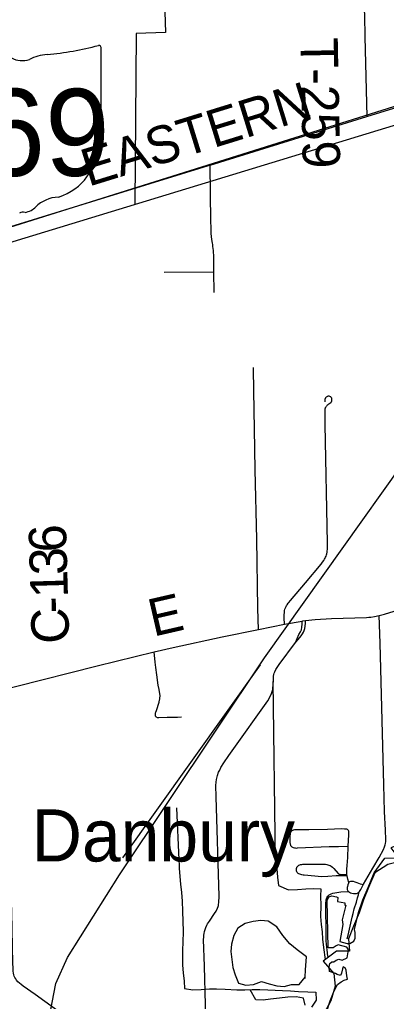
# Model space of a CAD drawing. Extents: x 0 to 34, y 0 to 22.
# Drawn here: x 6.521 to 6.799, y 17.764 to 18.509 of the extents above; entities that cross this region are included whole.
import ezdxf

# ---------------------------------------------------------------- set-up
doc = ezdxf.new("R2010")
doc.units = 0
for name, color, linetype in [('GM_X_Corporation', 7, 'Continuous'), ('GM_X_County_Road', 7, 'Continuous'), ('GM_X_County_Road_Text', 7, 'Continuous'), ('GM_X_Major_Lake', 7, 'Continuous'), ('GM_X_Minor_River', 7, 'Continuous'), ('GM_X_Rail_Line', 7, 'Continuous'), ('GM_X_State_Shield', 7, 'Continuous'), ('GM_X_Township_Road', 7, 'Continuous'), ('GM_X_Township_Road_Text', 7, 'Continuous'), ('GM_X_Unincorporated_Text', 7, 'Continuous')]:
    doc.layers.add(name, color=color, linetype=linetype)

msp = doc.modelspace()

# ---------------------------------------------------------------- linework, layer by layer
at = {"layer": 'GM_X_Corporation'}
msp.add_lwpolyline([(6.75001, 17.74515), (6.75626, 17.76472), (6.75934, 17.77212), (6.76173, 17.77704), (6.76463, 17.77893), (6.7669, 17.78019), (6.76942, 17.78094), (6.76879, 17.78359), (6.76841, 17.78788), (6.76766, 17.78952), (6.76602, 17.79027), (6.76551, 17.78876), (6.76488, 17.78548), (6.76413, 17.78372), (6.76161, 17.7846), (6.76034, 17.78536), (6.75581, 17.78674), (6.75556, 17.79015), (6.75606, 17.79292), (6.75745, 17.79406), (6.75909, 17.79406), (6.76085, 17.79544), (6.76287, 17.79607), (6.76526, 17.79532), (6.76917, 17.79708), (6.77021, 17.80321), (6.76879, 17.80527), (6.76236, 17.80704), (6.76072, 17.80628), (6.75858, 17.80477), (6.7548, 17.80477), (6.75404, 17.8407), (6.75518, 17.84347), (6.75757, 17.84422), (6.76097, 17.84334), (6.76211, 17.84297), (6.76186, 17.83994), (6.76728, 17.83881), (6.76728, 17.83717), (6.76803, 17.83704), (6.76526, 17.82595), (6.76589, 17.82254), (6.76362, 17.80969), (6.76904, 17.80817), (6.77106, 17.80817), (6.77409, 17.80981), (6.77522, 17.81221), (6.77522, 17.81649), (6.77459, 17.81876), (6.7777, 17.83145), (6.78111, 17.84114), (6.78491, 17.85065), (6.78965, 17.86168), (6.79761, 17.87284), (6.80592, 17.87307)], dxfattribs=at)
at = {"layer": 'GM_X_County_Road'}
for p, q in [((6.72168, 18.05033), (6.73492, 18.0526)), ((6.70197, 18.04626), (6.72168, 18.05033))]:
    msp.add_line(p, q, dxfattribs=at)
for points in [[(6.78405, 18.4351), (6.84223, 18.45323), (6.86594, 18.46076), (6.94588, 18.48653), (7.00216, 18.50455), (7.05407, 18.521), (7.05859, 18.52222), (7.0626, 18.52332)], [(6.6654, 18.39833), (6.76948, 18.43055), (6.78405, 18.4351)], [(6.4999, 18.34733), (6.50494, 18.34889), (6.53465, 18.35812), (6.66398, 18.39789), (6.6654, 18.39833)], [(6.79337, 18.0568), (6.79733, 18.05769), (6.8047, 18.06002), (6.81208, 18.06286)], [(6.73492, 18.0526), (6.73549, 18.0527), (6.73752, 18.05295), (6.74478, 18.05383), (6.75723, 18.05451), (6.78366, 18.05528), (6.78549, 18.05542), (6.78713, 18.05564), (6.78978, 18.056), (6.79337, 18.0568)], [(6.62285, 18.02934), (6.63733, 18.03241), (6.67444, 18.04055), (6.70197, 18.04626)], [(6.50954, 18.00084), (6.51779, 18.00287), (6.57959, 18.01851), (6.62285, 18.02934)]]:
    msp.add_lwpolyline(points, dxfattribs=at)
at = {"layer": 'GM_X_Major_Lake'}
for points in [[(6.80771, 17.89166), (6.81611, 17.88635), (6.82067, 17.87666), (6.82523, 17.86697), (6.81574, 17.87457), (6.81175, 17.88407), (6.80226, 17.88065), (6.80985, 17.87058), (6.79998, 17.86791), (6.79012, 17.86164), (6.78537, 17.85061), (6.78158, 17.84111), (6.77816, 17.83141), (6.7738, 17.82114)], [(6.80775, 17.89141), (6.81611, 17.88635), (6.82067, 17.87666), (6.82523, 17.86697), (6.81574, 17.87457), (6.81175, 17.88407), (6.80226, 17.88065), (6.80985, 17.87058), (6.79998, 17.86791), (6.79012, 17.86164), (6.78537, 17.85061), (6.78158, 17.84111), (6.77816, 17.83141), (6.7738, 17.82114)], [(6.7738, 17.82114), (6.77, 17.81164), (6.77076, 17.80213), (6.76108, 17.80232), (6.75084, 17.79472), (6.759, 17.78521), (6.75995, 17.77571), (6.75672, 17.76468), (6.7516, 17.75518)]]:
    msp.add_lwpolyline(points, dxfattribs=at)
at = {"layer": 'GM_X_Minor_River'}
for points in [[(6.62619, 18.663), (6.63139, 18.49883), (6.60918, 18.49815), (6.60813, 18.36834)], [(6.97961, 18.48166), (6.49479, 18.33379), (6.49906, 18.20382), (6.46737, 18.20215), (6.46468, 18.20803), (6.44, 18.20753), (6.41565, 18.21882)], [(6.70311, 18.01948), (6.59888, 17.87304)], [(6.71266, 18.0068), (6.71449, 17.8713)], [(6.63988, 17.91086), (6.6416, 17.87153)], [(6.6415, 17.87368), (6.64177, 17.86525), (6.6422, 17.85896), (6.64283, 17.85305), (6.64364, 17.84676), (6.64407, 17.84028), (6.64428, 17.83248), (6.64467, 17.82468), (6.6447, 17.81745), (6.64451, 17.80889), (6.6442, 17.80339), (6.64427, 17.79768), (6.64432, 17.79159), (6.64476, 17.78588), (6.64557, 17.77939), (6.64583, 17.77387), (6.65209, 17.77297), (6.65837, 17.77321), (6.66466, 17.77364), (6.67018, 17.77371), (6.67664, 17.77338), (6.68538, 17.77299), (6.69146, 17.77286), (6.69718, 17.77311), (6.70289, 17.77317), (6.70897, 17.77304), (6.71467, 17.77272), (6.72018, 17.77241), (6.72607, 17.77209), (6.73234, 17.77176), (6.73937, 17.77141), (6.74546, 17.77128), (6.74551, 17.76519), (6.74197, 17.75975)], [(6.71448, 17.87235), (6.71576, 17.86474), (6.71619, 17.85827), (6.717, 17.85197), (6.72473, 17.84876), (6.73139, 17.84899), (6.73768, 17.84942), (6.74359, 17.84986), (6.7491, 17.84955), (6.74897, 17.84385), (6.7492, 17.837), (6.74882, 17.82845), (6.74945, 17.82254), (6.75009, 17.81701), (6.75053, 17.81129), (6.75115, 17.805), (6.75246, 17.79593)], [(6.73822, 17.79804), (6.73133, 17.80316), (6.72572, 17.80785), (6.72035, 17.81424), (6.71593, 17.82081), (6.70936, 17.82495), (6.70367, 17.82546), (6.69775, 17.82483), (6.69182, 17.82325), (6.68623, 17.81976), (6.68325, 17.81412), (6.68139, 17.8075), (6.68089, 17.802), (6.6817, 17.79589)], [(6.73822, 17.79804), (6.73133, 17.80316), (6.72572, 17.80785), (6.72035, 17.81424), (6.71593, 17.82081), (6.70936, 17.82495), (6.70367, 17.82546), (6.69775, 17.82483), (6.69182, 17.82325), (6.68623, 17.81976), (6.68325, 17.81412), (6.68139, 17.8075), (6.68089, 17.802), (6.6817, 17.79589), (6.68252, 17.78998), (6.68411, 17.78424), (6.68663, 17.77791), (6.6923, 17.77645), (6.69802, 17.77689), (6.70416, 17.77923), (6.71002, 17.77758), (6.71569, 17.77593), (6.72139, 17.77542), (6.72694, 17.77701), (6.73265, 17.77708), (6.73733, 17.78249), (6.73765, 17.788), (6.73822, 17.79804)], [(6.6817, 17.79589), (6.68252, 17.78998), (6.68411, 17.78424), (6.68663, 17.77791), (6.6923, 17.77645), (6.69802, 17.77689), (6.70416, 17.77923), (6.71002, 17.77758), (6.71569, 17.77593), (6.72139, 17.77542), (6.72694, 17.77701), (6.73265, 17.77708), (6.73733, 17.78249), (6.73765, 17.788), (6.73822, 17.79804)], [(6.73731, 17.78154), (6.7373, 17.78292)], [(6.73724, 17.76119), (6.73603, 17.76673), (6.73035, 17.76762), (6.72425, 17.76737), (6.71777, 17.76657), (6.71109, 17.76576), (6.70537, 17.76513), (6.69986, 17.76525), (6.69564, 17.77304)]]:
    msp.add_lwpolyline(points, dxfattribs=at)
at = {"layer": 'GM_X_Rail_Line'}
for points in [[(4.40206, 18.19809), (4.68917, 18.19409), (5.00635, 18.18976), (5.15875, 18.1876), (5.36248, 18.18265), (5.7183, 18.17956), (5.93191, 18.17708), (6.25187, 18.2714), (6.49949, 18.34686), (7.04327, 18.51787), (7.07913, 18.52777), (7.1289, 18.52993), (7.24173, 18.53643), (7.28965, 18.56333), (7.33819, 18.59766)], [(6.61278, 17.58757), (6.59394, 17.63538), (6.57825, 17.66366), (6.55382, 17.71187), (6.54839, 17.72205), (6.54535, 17.73648), (6.54431, 17.75668), (6.54839, 17.77773), (6.55721, 17.79742), (6.59664, 17.86024), (6.70636, 18.02469), (6.87002, 18.25426), (6.98718, 18.4243), (7.02028, 18.46299), (7.04296, 18.48014), (7.06305, 18.4922), (7.09953, 18.50612), (7.1255, 18.5154), (7.18609, 18.52653), (7.59084, 18.53815)]]:
    msp.add_lwpolyline(points, dxfattribs=at)
at = {"layer": 'GM_X_State_Shield'}
for p, q in [((6.58263, 18.43502), (6.58263, 18.48737)), ((6.58262, 18.43504), (6.58263, 18.43502))]:
    msp.add_line(p, q, dxfattribs=at)
for centre, major_axis, start_param, end_param in [((6.52393, 18.6213), (0.17476, 0), 4.814394, 5.042369), ((6.5808, 18.48758), (0.00183, 0), 6.141152, 7.989035), ((6.52262, 18.48819), (0.01336, 0), 4.081561, 5.145723), ((6.54622, 18.45432), (0.03516, 0), 1.699011, 2.107814), ((6.58221, 18.43118), (0.00284, 0), 1.883978, 3.671073), ((6.58067, 18.43482), (0.00196, 0), 5.05454, 6.418171), ((6.56415, 18.42456), (0.01704, 0), 5.934695, 6.695948), ((6.5892, 18.41312), (0.0124, 0), 2.387724, 3.262537), ((6.53372, 18.40646), (0.04371, 0), 5.101752, 6.440018), ((6.55215, 18.35501), (0.02394, 0), 1.647645, 2.488434), ((6.52182, 18.37341), (0.01412, 0), 4.937069, 5.64225), ((6.52342, 18.35965), (0.00376, 0), 1.147584, 2.315152)]:
    msp.add_ellipse(centre, major_axis=major_axis, ratio=0.8, start_param=start_param, end_param=end_param, dxfattribs=at)
at = {"layer": 'GM_X_Township_Road'}
for p, q in [((6.63034, 18.3171), (6.66809, 18.31732)), ((6.66831, 18.30179), (6.66809, 18.31732)), ((6.76912, 17.85943), (6.76898, 17.86034))]:
    msp.add_line(p, q, dxfattribs=at)
for points in [[(6.78102, 18.51649), (6.78136, 18.51609), (6.78172, 18.5155), (6.78185, 18.51522), (6.78194, 18.51491), (6.78206, 18.51436), (6.78213, 18.51385), (6.78218, 18.51332), (6.78218, 18.51276), (6.78221, 18.5117), (6.7824, 18.4956), (6.78405, 18.4351)], [(6.66809, 18.31732), (6.66803, 18.32288), (6.66797, 18.32853), (6.66769, 18.33356), (6.66758, 18.33507), (6.66741, 18.33647), (6.66719, 18.338), (6.667, 18.33905), (6.66651, 18.34184), (6.66629, 18.34414), (6.66612, 18.34649), (6.66595, 18.34911), (6.66592, 18.35097), (6.66584, 18.35566), (6.6654, 18.39833)], [(6.70197, 18.04626), (6.70147, 18.06206), (6.70054, 18.11471), (6.69945, 18.16736), (6.69892, 18.19833), (6.69867, 18.21226), (6.69811, 18.24322), (6.6981, 18.24477)], [(6.72168, 18.05033), (6.72146, 18.0549), (6.72145, 18.05757), (6.7215, 18.05892), (6.72158, 18.05992), (6.72171, 18.06063), (6.72193, 18.06147), (6.72216, 18.06214), (6.72252, 18.06299), (6.72278, 18.06354), (6.72326, 18.06432), (6.7237, 18.06492), (6.72446, 18.06603), (6.72494, 18.06668), (6.72617, 18.0682), (6.73743, 18.08161), (6.74938, 18.09575), (6.75047, 18.09712), (6.75132, 18.09838), (6.75197, 18.09951), (6.75245, 18.10036), (6.75277, 18.10104), (6.75314, 18.10185), (6.7535, 18.10287), (6.75371, 18.10367), (6.75391, 18.10477), (6.75403, 18.10561), (6.75416, 18.10708), (6.75427, 18.10893), (6.75432, 18.11173), (6.75241, 18.20166), (6.75242, 18.21158), (6.75242, 18.2127), (6.75245, 18.21325), (6.75251, 18.21373), (6.75257, 18.21412), (6.75272, 18.21449), (6.75308, 18.21504), (6.75346, 18.21552), (6.75368, 18.21579), (6.754, 18.21611), (6.75432, 18.21643), (6.75481, 18.21683), (6.75533, 18.21726), (6.75666, 18.21835), (6.75698, 18.21866), (6.75719, 18.21891), (6.75746, 18.21949), (6.75753, 18.2198), (6.75758, 18.22018), (6.75758, 18.22076), (6.75752, 18.22121), (6.75741, 18.22152), (6.75726, 18.22181), (6.75706, 18.22212), (6.75671, 18.22248), (6.75643, 18.22271), (6.75595, 18.22297), (6.75558, 18.22308), (6.75526, 18.22309), (6.7545, 18.22303), (6.75415, 18.22293), (6.75366, 18.22271), (6.75321, 18.22237), (6.75281, 18.22193), (6.75259, 18.22156), (6.75245, 18.22126), (6.75225, 18.22049), (6.75219, 18.22018), (6.75216, 18.21974), (6.75214, 18.21927), (6.75215, 18.2188)], [(6.72987, 18.03633), (6.7321, 18.03862), (6.73421, 18.04133), (6.73525, 18.04282), (6.73597, 18.04425), (6.73652, 18.04535), (6.73701, 18.04688), (6.73726, 18.04868), (6.73746, 18.05088), (6.73752, 18.05295)], [(6.72987, 18.03633), (6.73259, 18.04237), (6.73369, 18.04445), (6.73441, 18.04599), (6.73473, 18.04796), (6.73492, 18.0503), (6.73492, 18.0526)], [(6.78119, 17.85249), (6.78153, 17.85313), (6.78856, 17.86523), (6.79335, 17.87336), (6.79655, 17.87924), (6.79743, 17.88127), (6.79792, 17.8828), (6.79818, 17.88399), (6.79835, 17.88531), (6.7984, 17.88698), (6.79809, 17.8941), (6.79747, 17.90811), (6.7968, 17.92834), (6.79408, 18.03589), (6.79337, 18.0568)], [(6.66247, 17.73212), (6.66096, 17.79089), (6.66033, 17.81112), (6.66036, 17.81292), (6.66049, 17.81433), (6.6607, 17.81576), (6.66098, 17.81723), (6.66144, 17.81876), (6.66203, 17.82031), (6.66283, 17.82198), (6.66336, 17.82297), (6.6648, 17.82512), (6.66868, 17.83073), (6.66973, 17.83251), (6.67081, 17.83474), (6.67131, 17.8361), (6.67151, 17.83693), (6.67161, 17.83772), (6.67177, 17.83925), (6.67201, 17.84391), (6.66981, 17.91936), (6.66965, 17.92789), (6.66977, 17.93036), (6.67006, 17.93254), (6.67074, 17.93555), (6.6717, 17.93798), (6.67259, 17.93963), (6.67342, 17.94146), (6.67568, 17.94511), (6.6795, 17.95062), (6.6819, 17.9541), (6.70887, 17.99219), (6.71051, 17.99484), (6.71181, 17.99765), (6.71233, 17.99919), (6.71265, 18.00062), (6.71289, 18.00231), (6.71302, 18.00369), (6.71324, 18.00837), (6.71328, 18.0095), (6.71337, 18.01084), (6.71354, 18.01197), (6.71382, 18.01295), (6.71419, 18.014), (6.715, 18.01579), (6.71748, 18.01975), (6.72987, 18.03633)], [(6.64356, 17.97971), (6.64045, 17.97956), (6.63264, 17.9794), (6.62635, 17.97916), (6.62565, 17.97922), (6.62525, 17.97927), (6.62492, 17.97939), (6.62463, 17.97956), (6.62427, 17.97993), (6.62395, 17.98035), (6.6238, 17.98087), (6.62374, 17.98129), (6.62375, 17.98164), (6.62385, 17.98255), (6.62397, 17.98308), (6.62412, 17.98354), (6.62448, 17.98465), (6.62651, 17.991), (6.62694, 17.9928), (6.62706, 17.99336), (6.62713, 17.99405), (6.62726, 17.99598), (6.62714, 17.99755), (6.62694, 17.99887), (6.62662, 18.00056), (6.62598, 18.00406), (6.62474, 18.01184), (6.62404, 18.01742), (6.62356, 18.02133), (6.62285, 18.02934)], [(6.76999, 17.88189), (6.77045, 17.89046), (6.77045, 17.89152), (6.77045, 17.89229), (6.77042, 17.89271), (6.7703, 17.89332), (6.77009, 17.89378), (6.76981, 17.89411), (6.76938, 17.89445), (6.76887, 17.89466), (6.76839, 17.89477), (6.76777, 17.89485), (6.76701, 17.89487), (6.76484, 17.89491), (6.75412, 17.89449), (6.74012, 17.89434), (6.73208, 17.89425), (6.73036, 17.89424), (6.72962, 17.89423), (6.7292, 17.89422), (6.72832, 17.89408), (6.72795, 17.89393), (6.72758, 17.89375), (6.72718, 17.89351), (6.7268, 17.89321), (6.7265, 17.89283), (6.72623, 17.89234), (6.72604, 17.89188), (6.72594, 17.89157), (6.72579, 17.8908), (6.72574, 17.88988), (6.72571, 17.88898), (6.72568, 17.88771), (6.72573, 17.88474), (6.7259, 17.88351), (6.72607, 17.88297), (6.72629, 17.88248), (6.72654, 17.88215), (6.72688, 17.88172), (6.72729, 17.88142), (6.72767, 17.88118), (6.72822, 17.88087), (6.7291, 17.88063), (6.72993, 17.88052), (6.73088, 17.88047), (6.73158, 17.88049), (6.75559, 17.88151), (6.76249, 17.8817), (6.76999, 17.88189)], [(6.76898, 17.86034), (6.76886, 17.86144), (6.7688, 17.86273), (6.7688, 17.86442), (6.769, 17.86718), (6.76964, 17.87329), (6.76999, 17.88189)], [(6.5666, 17.74487), (6.53253, 17.76935), (6.52346, 17.77584), (6.522, 17.7769), (6.52071, 17.77795), (6.51954, 17.77912), (6.51855, 17.78023), (6.5179, 17.78123), (6.51732, 17.78222), (6.51685, 17.78339), (6.51656, 17.78426), (6.51626, 17.78555), (6.51609, 17.78713), (6.51603, 17.78795), (6.51591, 17.78974), (6.5158, 17.79286), (6.51502, 17.83172), (6.51406, 17.86031), (6.51383, 17.86412), (6.51357, 17.86781), (6.51325, 17.87083)], [(6.76912, 17.85943), (6.76306, 17.85935), (6.76072, 17.85933), (6.7545, 17.85875), (6.74986, 17.85872), (6.73651, 17.85977), (6.73571, 17.85987), (6.73478, 17.86003), (6.7339, 17.86027), (6.73316, 17.86053), (6.73251, 17.86086), (6.73206, 17.86116), (6.73157, 17.86157), (6.73121, 17.86198), (6.73087, 17.86249), (6.73068, 17.86308), (6.73059, 17.86375), (6.73061, 17.86418), (6.73066, 17.86468), (6.73078, 17.86521), (6.7309, 17.86556), (6.73105, 17.86591), (6.73141, 17.86649), (6.73173, 17.86681), (6.73201, 17.86705), (6.7326, 17.86743), (6.73322, 17.86769), (6.7337, 17.86787), (6.73405, 17.86796), (6.73482, 17.86809), (6.73543, 17.86814), (6.73609, 17.86818), (6.73696, 17.86818), (6.75104, 17.86823), (6.75275, 17.8681), (6.75376, 17.86795), (6.75447, 17.86782), (6.7552, 17.86756), (6.75613, 17.86722), (6.75707, 17.8667), (6.75794, 17.866), (6.75895, 17.86496), (6.76222, 17.86117), (6.76255, 17.86089), (6.76298, 17.86066), (6.76353, 17.86054), (6.76416, 17.86046), (6.76474, 17.86042), (6.76662, 17.86038), (6.76898, 17.86034)], [(6.77046, 17.85442), (6.76974, 17.85696), (6.76912, 17.85943)], [(6.77046, 17.85442), (6.77012, 17.85384), (6.76965, 17.85257), (6.76925, 17.85131), (6.76902, 17.85051), (6.769, 17.84974), (6.76907, 17.84914), (6.76928, 17.84855), (6.76954, 17.84801), (6.77004, 17.84748), (6.77081, 17.84687), (6.77159, 17.84658), (6.77253, 17.84632), (6.77402, 17.84605), (6.77522, 17.84594), (6.77568, 17.84593), (6.77629, 17.84603), (6.77683, 17.84619), (6.77731, 17.84639), (6.77779, 17.84672), (6.77825, 17.84714)], [(6.78119, 17.85249), (6.77928, 17.85314), (6.77671, 17.85411), (6.77512, 17.85467), (6.77402, 17.855), (6.77325, 17.85512), (6.77242, 17.85514), (6.77161, 17.85505), (6.77098, 17.85482), (6.77046, 17.85442)], [(6.77825, 17.84714), (6.77856, 17.84754), (6.77939, 17.84902), (6.78119, 17.85249)], [(6.75446, 17.79825), (6.75412, 17.80095), (6.75338, 17.80753), (6.75323, 17.81), (6.75323, 17.81442), (6.75302, 17.8381), (6.75327, 17.8412), (6.75369, 17.84267), (6.75444, 17.84399), (6.75556, 17.84502), (6.75691, 17.84575), (6.75834, 17.8462), (6.76122, 17.84679), (6.76428, 17.84715), (6.77004, 17.84748)], [(6.76912, 17.81154), (6.76979, 17.81439), (6.77198, 17.82358), (6.77298, 17.82806), (6.77361, 17.8308), (6.77448, 17.83432), (6.77607, 17.83951), (6.77698, 17.84282), (6.77768, 17.84499), (6.77825, 17.84714)]]:
    msp.add_lwpolyline(points, dxfattribs=at)

# ---------------------------------------------------------------- texts
at = {"layer": 'GM_X_County_Road_Text'}
for s, height, rotation, p in [('EASTERN', 0.028409, 17.18123, (6.573, 18.38183)), ('6', 0.02841, 91.62367, (6.55658, 18.10515)), ('3', 0.02841, 91.61614, (6.55707, 18.08779)), ('1', 0.02841, 91.59474, (6.55755, 18.07042)), ('-', 0.02841, 91.55931, (6.55787, 18.05885)), ('E', 0.02841, 13.00632, (6.62225, 18.04063)), ('C', 0.02841, 91.49284, (6.55847, 18.03566))]:
    msp.add_text(s, height=height, rotation=rotation, dxfattribs=at).set_placement(p)
at = {"layer": 'GM_X_State_Shield'}
msp.add_text('269', height=0.065918, dxfattribs=at).set_placement((6.44208, 18.39016))
at = {"layer": 'GM_X_Township_Road_Text'}
msp.add_text('T-259', height=0.028409, rotation=271.1227, dxfattribs=at).set_placement((6.73357, 18.49473))
at = {"layer": 'GM_X_Unincorporated_Text'}
msp.add_text('Danbury', height=0.039489, rotation=0.00001, dxfattribs=at).set_placement((6.52995, 17.87026))

doc.saveas('drawing.dxf')
